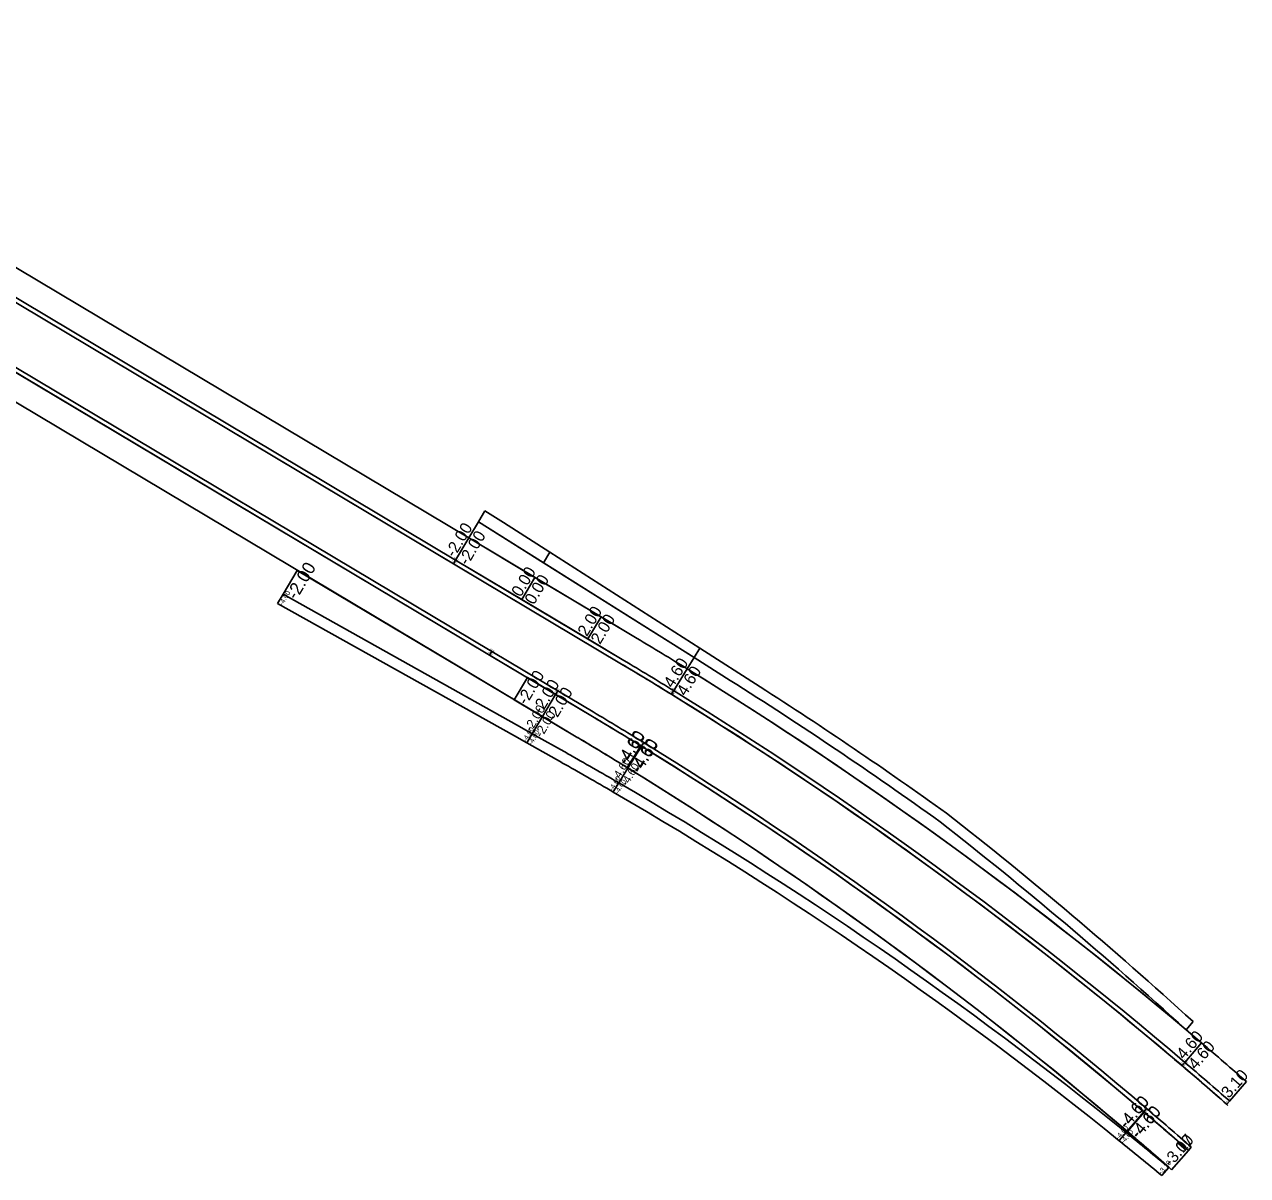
# Model space of a CAD drawing. Extents: x 2342222 to 2351711, y 366548 to 372860.
# Drawn here: x 2350568 to 2351711, y 366548 to 367623 of the extents above; entities that cross this region are included whole.
import ezdxf

# ---------------------------------------------------------------- set-up
doc = ezdxf.new("R2010")
doc.units = 0
for name, color, linetype in [('RD_PD_PaveShd', 7, 'Continuous'), ('RD_PD_SuperShp_BL_EB_526', 7, 'Continuous'), ('RD_PD_SuperShp_BL_WB_526', 7, 'Continuous'), ('RD_PD_SuperShp_EB_526', 7, 'Continuous')]:
    doc.layers.add(name, color=color, linetype=linetype)

msp = doc.modelspace()

# ---------------------------------------------------------------- linework, layer by layer
at = {"layer": 'RD_PD_PaveShd'}
msp.add_line((2349506.9, 367991.4), (2351125.7, 367025.5), dxfattribs=at)
msp.add_arc((2349155.3, 363723), 3845.7, 48.7231, 59.1785, dxfattribs=at)
at = {"layer": 'RD_PD_SuperShp_BL_EB_526'}
for p, q in [((2348584, 368476.8), (2351064, 366997.1)), ((2351051.7, 366976.5), (2348571.6, 368456.3)), ((2350386.3, 367401.5), (2351002.2, 367034)), ((2351004.3, 367037.5), (2350388.4, 367404.9)), ((2350822.6, 367113.2), (2350809.3, 367090.9)), ((2351051.7, 366976.5), (2350822.6, 367113.2)), ((2350809.3, 367090.9), (2350804.2, 367082.3)), ((2350804.2, 367082.3), (2351025.4, 366958.5)), ((2350809.3, 367090.9), (2351030.3, 366967.2)), ((2351030.3, 366967.2), (2350809.3, 367090.9)), ((2351002.2, 367034), (2351004.3, 367037.5)), ((2351004.3, 367037.5), (2351002.2, 367034)), ((2351002.2, 367034), (2351064, 366997.1)), ((2351066.1, 367000.6), (2351004.3, 367037.5)), ((2351064, 366997.1), (2351066.1, 367000.6)), ((2351066.1, 367000.6), (2351064, 366997.1)), ((2351099.1, 366980.9), (2351066.1, 367000.6)), ((2351064, 366997.1), (2351051.7, 366976.5)), ((2351051.7, 366976.5), (2351064, 366997.1)), ((2351064, 366997.1), (2351097, 366977.5)), ((2351064, 366997.1), (2351097, 366977.5)), ((2351030.3, 366967.2), (2351042.2, 366960.5)), ((2351042.2, 366960.5), (2351030.3, 366967.2)), ((2351042.2, 366960.5), (2351051.7, 366976.5)), ((2351051.7, 366976.5), (2351042.2, 366960.5)), ((2351084.7, 366956.8), (2351051.7, 366976.5)), ((2351084.7, 366956.8), (2351051.7, 366976.5)), ((2351025.4, 366958.5), (2351037.1, 366951.9)), ((2351037.1, 366951.9), (2351042.2, 366960.5)), ((2351042.2, 366960.5), (2351037.1, 366951.9)), ((2351042.2, 366960.5), (2351074.8, 366942.2)), ((2351074.8, 366942.2), (2351042.2, 366960.5)), ((2351037.1, 366951.9), (2351069.9, 366933.5)), ((2351144.2, 366948.8), (2351131.6, 366928.4)), ((2351131.6, 366928.4), (2351144.2, 366948.8)), ((2351144.2, 366948.8), (2351146.3, 366952.2)), ((2351146.3, 366952.2), (2351144.2, 366948.8)), ((2351123.1, 366914.6), (2351131.6, 366928.4)), ((2351131.6, 366928.4), (2351123.1, 366914.6)), ((2351117.8, 366906.1), (2351123.1, 366914.6)), ((2351123.1, 366914.6), (2351117.8, 366906.1)), ((2351613.6, 366607.2), (2351598.1, 366588.9)), ((2351613.6, 366607.2), (2351598.1, 366588.9)), ((2351613.6, 366607.2), (2351616.2, 366610.2)), ((2351616.2, 366610.2), (2351613.6, 366607.2)), ((2351597.1, 366587.8), (2351598.1, 366588.9)), ((2351598.1, 366588.9), (2351597.1, 366587.8)), ((2351590.6, 366580.2), (2351597.1, 366587.8)), ((2351597.1, 366587.8), (2351590.6, 366580.2)), ((2351639.5, 366553), (2351655.4, 366571.1)), ((2351655.4, 366571.1), (2351658, 366574.1)), ((2351630.4, 366547.6), (2351637, 366555.1)), ((2351637, 366555.1), (2351637.1, 366555.2)), ((2351639.5, 366553), (2351639.5, 366553))]:
    msp.add_line(p, q, dxfattribs=at)
for centre, radius, start, end in [((2349155.3, 363723), 3789.7, 58.3441, 59.1785), ((2349155.3, 363723), 3789.7, 58.3441, 59.1785), ((2349155.3, 363723), 3793.7, 58.3441, 59.1785), ((2349155.3, 363723), 3765.7, 58.3441, 59.1785), ((2349155.3, 363723), 3765.7, 58.3441, 59.1785), ((2349155.3, 363723), 3789.7, 49.5576, 58.3441), ((2349155.3, 363723), 3789.7, 49.5576, 58.3441), ((2349155.3, 363723), 3793.7, 49.5576, 58.3441), ((2349233.2, 363665.5), 3748.7, 59.8183, 60.6623), ((2349233.2, 363665.5), 3758.7, 59.8144, 60.6623), ((2349233.2, 363665.5), 3758.7, 59.8144, 60.6623), ((2349155.3, 363723), 3765.7, 49.5576, 58.3441), ((2349155.3, 363723), 3765.7, 49.5576, 58.3441), ((2349233.2, 363665.5), 3758.7, 51.0292, 59.8144), ((2349233.2, 363665.5), 3758.7, 51.0292, 59.8144), ((2349233.2, 363665.5), 3748.7, 51.0332, 59.8183), ((2349155.3, 363723), 3789.7, 48.7232, 49.5576), ((2349155.3, 363723), 3789.7, 48.7232, 49.5576), ((2349155.3, 363723), 3793.7, 48.7231, 49.5576), ((2349155.3, 363723), 3765.7, 48.7232, 49.5576), ((2349155.3, 363723), 3765.7, 48.7726, 49.5576), ((2349233.2, 363665.5), 3748.7, 50.2466, 51.0332), ((2349233.2, 363665.5), 3758.7, 50.2427, 51.0292), ((2349233.2, 363665.5), 3758.7, 50.2427, 51.0292)]:
    msp.add_arc(centre, radius, start, end, dxfattribs=at)
at = {"layer": 'RD_PD_SuperShp_BL_WB_526'}
for p, q in [((2350982.8, 367143.5), (2348626.9, 368549)), ((2348614.8, 368528.3), (2350970.5, 367122.8)), ((2349506.9, 367991.4), (2350968.4, 367119.4)), ((2350970.5, 367122.8), (2349511.2, 367993.5)), ((2350997.9, 367168.8), (2350991.8, 367158.6)), ((2351015.2, 367157.8), (2350997.9, 367168.8)), ((2350991.8, 367158.6), (2350982.8, 367143.5)), ((2351193.3, 367031.6), (2350991.8, 367158.6)), ((2350991.8, 367158.6), (2351052.7, 367120.2)), ((2351058.6, 367130.1), (2351015.2, 367157.8)), ((2350982.8, 367143.5), (2350970.5, 367122.8)), ((2350970.5, 367122.8), (2350982.8, 367143.5)), ((2351044.6, 367106.6), (2350982.8, 367143.5)), ((2350982.8, 367143.5), (2351140.1, 367049.6)), ((2351052.7, 367120.2), (2351058.6, 367130.1)), ((2351058.6, 367130.1), (2351052.7, 367120.2)), ((2351198.7, 367040.4), (2351058.6, 367130.1)), ((2350970.5, 367122.8), (2350968.4, 367119.4)), ((2350968.4, 367119.4), (2350970.5, 367122.8)), ((2350968.4, 367119.4), (2351125.7, 367025.5)), ((2350970.5, 367122.8), (2351032.3, 367086)), ((2351127.8, 367029), (2350970.5, 367122.8)), ((2351052.7, 367120.2), (2351193.3, 367031.6)), ((2351032.3, 367086), (2351044.6, 367106.6)), ((2351032.3, 367086), (2351044.6, 367106.6)), ((2351044.6, 367106.6), (2351106.4, 367069.7)), ((2351094.1, 367049.1), (2351032.3, 367086)), ((2351106.4, 367069.7), (2351094.1, 367049.1)), ((2351106.4, 367069.7), (2351094.1, 367049.1)), ((2351140.1, 367049.6), (2351106.4, 367069.7)), ((2351094.1, 367049.1), (2351127.8, 367029)), ((2351193.3, 367031.6), (2351198.7, 367040.4)), ((2351198.7, 367040.4), (2351193.3, 367031.6)), ((2351255, 367004.4), (2351198.7, 367040.4)), ((2351186.9, 367021.2), (2351193.3, 367031.6)), ((2351193.3, 367031.6), (2351186.9, 367021.2)), ((2351227, 367010.4), (2351193.3, 367031.6)), ((2351193.3, 367031.6), (2351227, 367010.4)), ((2351174.3, 367000.8), (2351186.9, 367021.2)), ((2351186.9, 367021.2), (2351174.3, 367000.8)), ((2351174.3, 367000.8), (2351172.2, 366997.4)), ((2351172.2, 366997.4), (2351174.3, 367000.8)), ((2351653.2, 366683.7), (2351659.7, 366691.4)), ((2351652, 366653.3), (2351667.5, 366671.6)), ((2351652, 366653.3), (2351667.5, 366671.6)), ((2351649.4, 366650.3), (2351652, 366653.3)), ((2351652, 366653.3), (2351649.4, 366650.3)), ((2351709.5, 366635.3), (2351693.7, 366617.2)), ((2351691.1, 366614.2), (2351693.7, 366617.2))]:
    msp.add_line(p, q, dxfattribs=at)
for centre, radius, start, end in [((2349155.3, 363723), 3873.7, 58.3686, 59.1785), ((2349155.3, 363723), 3873.7, 58.3686, 59.1785), ((2349155.3, 363723), 3845.7, 58.3686, 59.1785), ((2349155.3, 363723), 3849.7, 58.3686, 59.1785), ((2349155.3, 363723), 3849.7, 58.3686, 59.1785), ((2349155.3, 363723), 3873.7, 49.5692, 58.3686), ((2349155.3, 363723), 3873.7, 49.8527, 58.3686), ((2349155.3, 363723), 3849.7, 49.5692, 58.3686), ((2349155.3, 363723), 3849.7, 49.5692, 58.3686), ((2349155.3, 363723), 3885.7, 54.29, 57.7811), ((2349155.3, 363723), 3885.7, 54.29, 57.7811), ((2349155.3, 363723), 3895.7, 54.2871, 57.3854), ((2349155.3, 363723), 3845.7, 49.5692, 58.3686), ((2349068, 363859.6), 3838.7, 47.5354, 52.0384), ((2349068, 363859.6), 3828.7, 47.5354, 52.0354), ((2349068, 363859.6), 3828.7, 47.5354, 52.0354), ((2349155.3, 363723), 3873.7, 49.8467, 49.8527), ((2349155.3, 363723), 3873.7, 48.7478, 49.5692), ((2349155.3, 363723), 3845.7, 48.7478, 49.5692), ((2349155.3, 363723), 3849.7, 48.7478, 49.5692), ((2349155.3, 363723), 3849.7, 48.7478, 49.5692)]:
    msp.add_arc(centre, radius, start, end, dxfattribs=at)
at = {"layer": 'RD_PD_SuperShp_EB_526'}
for p, q in [((2351025.3, 366992.3), (2351037.6, 367012.9)), ((2351037.6, 367012.9), (2351097, 366977.5)), ((2351084.7, 366956.8), (2351025.3, 366992.3)), ((2351143.5, 366949.3), (2351130.9, 366928.8)), ((2351130.9, 366928.8), (2351143.5, 366949.3)), ((2351613.9, 366606.9), (2351598.4, 366588.7)), ((2351598.4, 366588.7), (2351613.9, 366606.9)), ((2351655.4, 366571.1), (2351639.5, 366553))]:
    msp.add_line(p, q, dxfattribs=at)
for radius, start, end in [(3789.7, 58.3569, 59.1785), (3765.7, 58.3569, 59.1785), (3789.7, 49.5519, 58.3569), (3765.7, 49.5519, 58.3569), (3789.7, 48.7231, 49.5519), (3765.7, 48.7231, 49.5519)]:
    msp.add_arc((2349155.3, 363723), radius, start, end, dxfattribs=at)

# ---------------------------------------------------------------- texts
at = {"layer": 'RD_PD_SuperShp_BL_EB_526'}
for s, height, rotation, p in [('-2.00', 11.96, 59.1785, (2350821.8, 367084.9)), ('-4.00', 4.6, 59.1785, (2350809, 367080)), ('-2.00', 1.84, 59.1785, (2351002.1, 367034.3)), ('-2.00', 1.84, 59.1785, (2351004.1, 367033.1)), ('-2.00', 11.04, 59.1785, (2351050.8, 366978.2)), ('-2.00', 11.04, 59.1785, (2351063.2, 366970.8)), ('-2.00', 1.84, 59.1785, (2351063.9, 366997.4)), ('-2.00', 1.84, 59.1785, (2351065.9, 366996.2)), ('-2.00', 8.58, 59.1785, (2351041.4, 366961.7)), ('-2.00', 8.58, 59.1785, (2351051.1, 366956.2)), ('-4.00', 4.6, 59.1785, (2351036.6, 366952.6)), ('-4.00', 4.6, 59.1785, (2351041.9, 366949.6)), ('-4.60', 11.04, 58.3441, (2351130.7, 366930.1)), ('-4.60', 11.04, 58.3441, (2351143, 366922.5)), ('4.60', 1.84, 58.3441, (2351144.1, 366949.1)), ('4.60', 1.84, 58.3441, (2351146.1, 366947.9)), ('-4.60', 7.48, 58.3441, (2351122.4, 366915.6)), ('-4.60', 7.48, 58.3441, (2351130.8, 366910.7)), ('-4.60', 4.6, 58.3441, (2351117.4, 366906.7)), ('-4.60', 4.6, 58.3441, (2351122.6, 366903.7)), ('-4.60', 11.04, 49.5576, (2351597.4, 366590.7)), ('-4.60', 11.04, 49.5576, (2351608.4, 366581.4)), ('4.60', 1.84, 49.5576, (2351613.5, 366607.5)), ('4.60', 1.84, 49.5576, (2351615.4, 366605.9)), ('-4.60', 4.6, 49.5576, (2351590.3, 366580.9)), ('-4.60', 4.6, 49.5576, (2351595, 366577.1)), ('-4.60', 0.661, 49.5576, (2351597.1, 366587.9)), ('-4.60', 0.661, 49.5576, (2351597.8, 366587.4)), ('-3.10', 11.04, 48.7232, (2351638.9, 366554.9)), ('3.10', 1.84, 48.6679, (2351655.3, 366571.4)), ('-3.10', 4.6, 48.7726, (2351630.1, 366548.3)), ('-3.10', 0.0519, 48.7726, (2351637, 366555.1))]:
    msp.add_text(s, height=height, rotation=rotation, dxfattribs=at).set_placement(p)
at = {"layer": 'RD_PD_SuperShp_BL_WB_526'}
for s, height, rotation, p in [('-2.00', 11.04, 59.1785, (2350969.5, 367124.5)), ('-2.00', 11.04, 59.1785, (2350981.9, 367117.1)), ('-2.00', 1.84, 59.1785, (2350968.2, 367119.7)), ('-2.00', 1.84, 59.1785, (2350970.3, 367118.5)), ('0.00', 11.04, 59.1785, (2351031.3, 367087.6)), ('0.00', 11.04, 59.1785, (2351043.7, 367080.3)), ('2.00', 11.04, 59.1785, (2351093.2, 367050.7)), ('2.00', 11.04, 59.1785, (2351105.5, 367043.4)), ('4.60', 11.04, 58.3686, (2351173.4, 367002.5)), ('4.60', 11.04, 58.3686, (2351185.6, 366994.9)), ('-4.60', 1.84, 58.3686, (2351172, 366997.7)), ('-4.60', 1.84, 58.3686, (2351174.1, 366996.4)), ('4.60', 11.04, 49.5692, (2351651.3, 366655.2)), ('4.60', 11.04, 49.5692, (2351662.3, 366645.8)), ('-4.60', 1.84, 49.5692, (2351649.3, 366650.6)), ('-3.10', 1.84, 49.5692, (2351651.1, 366649)), ('3.10', 11.04, 48.7478, (2351693.1, 366619.1)), ('-3.10', 1.84, 48.7478, (2351691, 366614.5))]:
    msp.add_text(s, height=height, rotation=rotation, dxfattribs=at).set_placement(p)
at = {"layer": 'RD_PD_SuperShp_EB_526'}
for s, rotation, p in [('-2.00', 59.1785, (2351036.7, 366986.6)), ('-4.60', 58.3569, (2351130, 366930.5)), ('-4.60', 58.3569, (2351142.2, 366923)), ('-4.60', 49.5519, (2351597.7, 366590.5)), ('-4.60', 49.5519, (2351608.7, 366581.1)), ('-3.07', 48.7231, (2351638.9, 366554.9))]:
    msp.add_text(s, height=11.04, rotation=rotation, dxfattribs=at).set_placement(p)

doc.saveas('drawing.dxf')
